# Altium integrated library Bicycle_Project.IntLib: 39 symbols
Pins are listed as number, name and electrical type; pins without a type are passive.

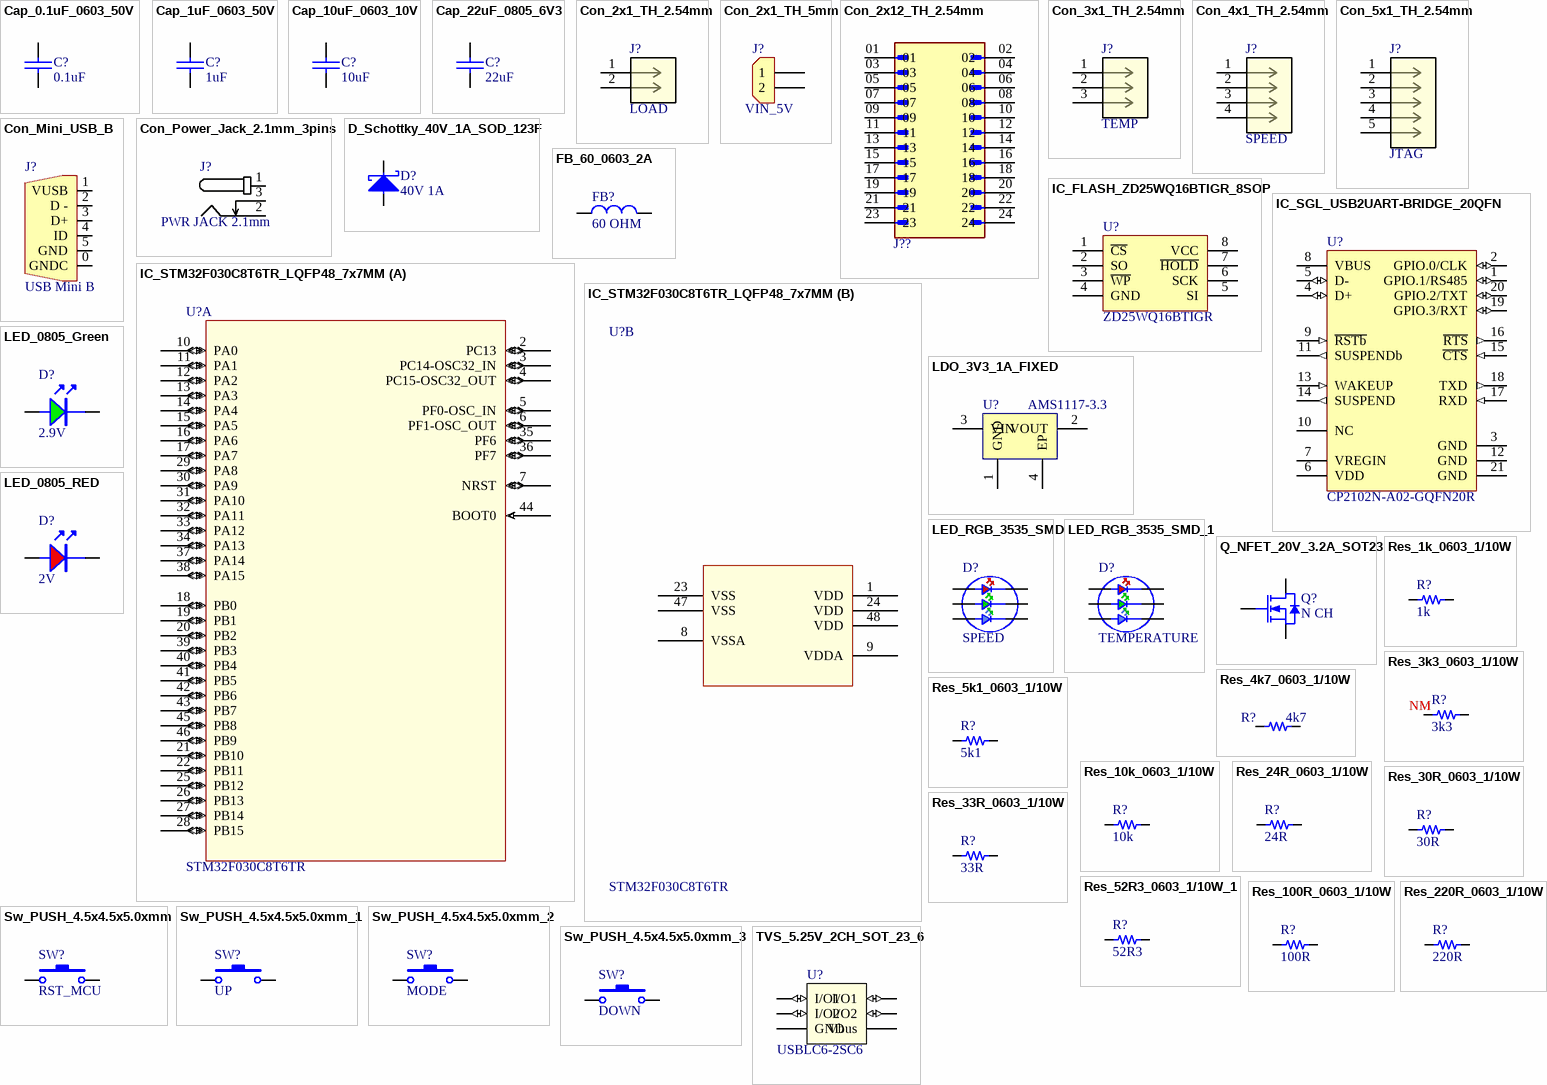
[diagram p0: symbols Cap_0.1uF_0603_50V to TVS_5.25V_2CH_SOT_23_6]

## Cap_0.1uF_0603_50V
designator C?, comment value 0.1uF  (hidden comment: 0.1uF 50V)
50V 100nF Y5V -20%~+80% 0603 Multilayer Ceramic Capacitors MLCC - SMD/SMT ROHS; Manufacturer: Walsin Tech Corp; Manufacturer Part Number: 0603F104Z500CT
footprint 0603_cap
pins: 1, 2

## Cap_1uF_0603_50V
designator C?, comment value 1uF  (hidden comment: 1uF 50V)
50V 1uF X5R ±10% 0603 Multilayer Ceramic Capacitors MLCC - SMD/SMT ROHS; Manufacturer: Samsung Electro-Mechanics; Manufacturer Part Number: CL10A105KB8NNNC
footprint 0603_cap
pins: 1, 2

## Cap_10uF_0603_10V
designator C?, comment value 10uF  (hidden comment: 10uF 10V)
10V 10uF X5R ±10% 0603 Multilayer Ceramic Capacitors MLCC - SMD/SMT ROHS; Manufacturer: CCTC; Manufacturer Part Number: TCC0603X5R106K100CT
footprint 0603_cap
pins: 1, 2

## Cap_22uF_0805_6V3
designator C?, comment value 22uF  (hidden comment: 22uF 6V3)
6.3V 22uF X5R ±20% 0805 Multilayer Ceramic Capacitors MLCC - SMD/SMT ROHS; Manufacturer: Samsung Electro-Mechanics; Manufacturer Part Number: CL21A226MQQNNNE
footprint 0603_cap
pins: 1, 2

## Con_2x1_TH_2.54mm
designator J?, comment LOAD
CONN HEADER VERT 2POS 2.54MM; Manufacturer: Samtec Inc.; Manufacturer Part Number: TS-102-T-A
footprint CON_2X1_TH_2.54mm
pins: 1, 2

## Con_2x1_TH_5mm
designator J?, comment VIN_5V
2POS 5MM; Manufacturer: JILN; Manufacturer Part Number: JL126-50002G01
footprint CON_2x1_TH_5MM
pins: 1, 2

## Con_2x12_TH_2.54mm
designator J??, comment 10129381-924001BLF  (value not drawn)
CONN HEADER VERT 24POS 2.54MM; Manufacturer: Amphenol ICC (FCI)
footprint CON_2x12_th_2.54MM
pins: 01, 02, 03, 04, 05, 06, 07, 08, 09, 10, 11, 12, 13, 14, 15, 16, 17, 18, 19, 20, 21, 22, 23, 24

## Con_3x1_TH_2.54mm
designator J?, comment TEMP
CONN HEADER VERT 3POS 2.54MM; Manufacturer: Samtec Inc.; Manufacturer Part Number: TS-103-T-A
footprint CON_3X1_TH_2.54mm
pins: 1, 2, 3

## Con_4x1_TH_2.54mm
designator J?, comment SPEED
CONN HEADER VERT 4POS 2.54MM; Manufacturer: Samtec Inc.; Manufacturer Part Number: TS-104-T-A
footprint CON_4X1_TH_2.54mm
pins: 1, 2, 3, 4

## Con_5x1_TH_2.54mm
designator J?, comment JTAG
CONN HEADER VERT 5POS 2.54MM; Manufacturer: Samtec Inc.; Manufacturer Part Number: TS-105-T-A
footprint CON_5X1_TH_2.54mm
pins: 1, 2, 3, 4, 5

## Con_Mini_USB_B
designator J?, comment USB Mini B
CONN RCPT USB2.0 MINI B SMD R/A; Manufacturer Part Number: KH-MINI-SMT-5P-Cu; Manufacturer: EDAC Inc.
footprint CON_5x1_SMD_miniUSB_B (20190328 / V-A.Patino)
pins: 0 GNDC, 1 VUSB, 2 D -, 3 D+, 4 ID, 5 GND

## Con_Power_Jack_2.1mm_3pins
designator J?, comment PWR JACK 2.1mm
CONN PWR JACK 2X5.5MM SOLDER; Manufacturer: HCTL; Manufacturer Part Number: HC-DC-005-2.0T
footprint CON_POWER_BARREL_2.1MM_3CONN (/ 20190222 / C-A.Serna.A)
pins: 1, 2, 3

## D_Schottky_40V_1A_SOD_123F
designator D?, comment 40V 1A
DIODE SCHOTTKY 40V 1A SOD123F; Manufacturer: Shanghai Prisemi Elec; Manufacturer Part Number: PSBD1DF40V1H
footprint SOD_123 (/ 20191030 / V-A.Patino)
pins: 1, 2

## FB_60_0603_2A
designator FB?, comment value 60 OHM  (hidden comment: 60OHM 2A)
2A 1 100mΩ 60Ω@100MHz ±25% 0603 Ferrite Beads ROHS; Manufacturer: TAI-TECH; Manufacturer Part Number: HCB1608KF-600T20
footprint 0603_fb
pins: 1, 2

## IC_FLASH_ZD25WQ16BTIGR_8SOP
designator U?, comment ZD25WQ16BTIGR
IC FLASH 16M SPI 85MHZ 8SOP; Manufacturer: Zetta
footprint SOIC_8_3.9mm (/ 20190225 / C-A.Serna.A)
pins: 1 ~{CS}, 2 SO, 3 ~{WP}, 4 GND, 5 SI, 6 SCK, 7 ~{HOLD}, 8 VCC

## IC_SGL_USB2UART-BRIDGE_20QFN
designator U?, comment CP2102N-A02-GQFN20R
IC USB TO UART BRIDGE QFN20; Manufacturer: Silicon Labs
footprint WFQFN_20_EP_3X3MM (QFN_20/ 20210809/ V-A.Patino)
pins: 1 GPIO.1/RS485 (io), 2 GPIO.0/CLK (io), 3 GND (power) "Ground", 4 D+ (io) "USB Data Positive", 5 D- (io) "USB Data Negative", 6 VDD (power) "Supply Power Input/5V Regulator Output", 7 VREGIN (power) "5V Regulator Input", 8 VBUS (power) "Digital Input. VBUS Sense Input. This pin should be connected to the VBUS signal of a USBnetwork. A 5 V signal on this pin indicates a USB network connection", 9 ~{RSTb} (in) "Active-low Reset", 10 NC "No Connect (leave this pin floating)", 11 SUSPENDb (out) "Digital Output. This pin is driven low when the device enters the USB suspend state.", 12 GND (power) "Ground", 13 WAKEUP (in) "Digital Input. Remote USB wakeup interrupt input.", 14 SUSPEND (out) "Digital Output. This pin is driven high when the device enters the USB suspend state", 15 ~{CTS} (in) "Digital Input. Clear To Send control input (active low).", 16 ~{RTS} (out) "Digital Output. Ready To Send control output (active low).", 17 RXD (in) "Digital Input. Asynchronous data input (UART Receive).", 18 TXD (out) "Digital Output. Asynchronous data output (UART Transmit)", 19 GPIO.3/RXT (io), 20 GPIO.2/TXT (io), 21 GND (power) "Ground"

## IC_STM32F030C8T6TR_LQFP48_7x7MM
designator U?, comment STM32F030C8T6TR
IC MCU 32BIT 64KB FLASH 48LQFP; Manufacturer: STMicroelectronics
footprint LQFP48_7x7mm
part A pins: 2 PC13 (io), 3 PC14-OSC32_IN (io), 4 PC15-OSC32_OUT (io), 5 PF0-OSC_IN (io), 6 PF1-OSC_OUT (io), 7 NRST (io), 10 PA0 (io), 11 PA1 (io), 12 PA2 (io), 13 PA3 (io), 14 PA4 (io), 15 PA5 (io), 16 PA6 (io), 17 PA7 (io), 18 PB0 (io), 19 PB1 (io), 20 PB2 (io), 21 PB10 (io), 22 PB11 (io), 25 PB12 (io), 26 PB13 (io), 27 PB14 (io), 28 PB15 (io), 29 PA8 (io), 30 PA9 (io), 31 PA10 (io), 32 PA11 (io), 33 PA12 (io), 34 PA13 (io), 35 PF6 (io), 36 PF7 (io), 37 PA14 (io), 38 PA15 (io), 39 PB3 (io), 40 PB4 (io), 41 PB5 (io), 42 PB6 (io), 43 PB7 (io), 44 BOOT0 (in), 45 PB8 (io), 46 PB9 (io)
part B pins: 1 VDD (power), 8 VSSA (power), 9 VDDA (power), 23 VSS (power), 24 VDD (power), 47 VSS (power), 48 VDD (power)

## LDO_3V3_1A_FIXED
designator U?, comment AMS1117-3.3
1A 60dB@(120Hz) Fixed 3.3V Positive 18V SOT-223 Linear Voltage Regulators (LDO) ROHS; Manufacturer: UMW(Youtai Semiconductor Co., Ltd.)
footprint SOT_223 (TO-261-4, TO-261AA / 20190829 / M-X.Arias)
pins: 1 GND, 2 VOUT, 3 VIN, 4 EP

## LED_0805_Green
designator D?, comment 2.9V
LED GREEN CLEAR 0805 SMD; Manufacturer: XINGLIGHT; Manufacturer Part Number: XL-2012UGC
footprint 0805_LED
pins: 1 A, 2

## LED_0805_RED
designator D?, comment 2V
LED RED CLEAR 0805 SMD; Manufacturer: XINGLIGHT; Manufacturer Part Number: XL-2012SURC
footprint 0805_LED
pins: 1 A, 2

## LED_RGB_3535_SMD
designator D?, comment SPEED
-30℃~+85℃ RGB 110° 3535(mm) Light Emitting Diodes (LED) ROHS; Manufacturer: Foshan NationStar Optoelectronics; Manufacturer Part Number: RS-3535MWAM
footprint RGB_NS_3.5X3.7
pins: 1, 2, 3, 4, 5, 6

## LED_RGB_3535_SMD_1
designator D?, comment TEMPERATURE
-30℃~+85℃ RGB 110° 3535(mm) Light Emitting Diodes (LED) ROHS; Manufacturer: Foshan NationStar Optoelectronics; Manufacturer Part Number: RS-3535MWAM
footprint RGB_NS_3.5X3.7
pins: 1, 2, 3, 4, 5, 6

## Q_NFET_20V_3.2A_SOT23
designator Q?, comment N CH
MOSFET N-CH 20V SOT23; Manufacturer: Doeshare; Manufacturer Part Number: DN2302S
footprint SOT_23_3 (TO-236-3, SC-59/ 20220901 / V-A.Patino)
pins: 1 G, 2 S, 3 D

## Res_1k_0603_1/10W
designator R?, comment value 1k  (hidden comment: 1k 1/10W)
RES SMD 1k OHM 5% 1/10W 0603; Manufacturer: FOJAN; Manufacturer Part Number: FRC0603J102 TS
footprint 0603_res (1608 Metric / 20190225 / C-A.Serna.A)
pins: 1, 2

## Res_3k3_0603_1/10W
designator R?, comment value 3k3  Usage: NM  (hidden comment: 3k3 1/10W)
RES SMD 3k3 OHM 5% 1/10W 0603; Manufacturer: FOJAN; Manufacturer Part Number: FRC0603J332 TS
footprint 0603_res (1608 Metric / 20190225 / C-A.Serna.A)
pins: 1, 2

## Res_4k7_0603_1/10W
designator R?, comment value 4k7  (hidden comment: 4k7 1/10W)
RES SMD 4k7 OHM 5% 1/10W 0603; Manufacturer: FOJAN; Manufacturer Part Number: FRC0603J472 TS
footprint 0603_res (1608 Metric / 20190225 / C-A.Serna.A)
pins: 1, 2

## Res_5k1_0603_1/10W
designator R?, comment value 5k1  (hidden comment: 5k1 1/10W)
RES SMD 5k1 OHM 5% 1/10W 0603; Manufacturer: FOJAN; Manufacturer Part Number: FRC0603J512 TS
footprint 0603_res (1608 Metric / 20190225 / C-A.Serna.A)
pins: 1, 2

## Res_10k_0603_1/10W
designator R?, comment value 10k  (hidden comment: 10k 1/10W)
RES SMD 10k OHM 5% 1/10W 0603; Manufacturer: FOJAN; Manufacturer Part Number: FRC0603J103TS
footprint 0603_res (1608 Metric / 20190225 / C-A.Serna.A)
pins: 1, 2

## Res_24R_0603_1/10W
designator R?, comment value 24R  (hidden comment: 24R 1/10W)
RES SMD 24R OHM 5% 1/10W 0603; Manufacturer: FOJAN; Manufacturer Part Number: FRC0603J240 TS
footprint 0603_res (1608 Metric / 20190225 / C-A.Serna.A)
pins: 1, 2

## Res_30R_0603_1/10W
designator R?, comment value 30R  (hidden comment: 30 1/10W)
RES SMD 30R OHM 1% 1/10W 0603; Manufacturer: FOJAN; Manufacturer Part Number: FRC0603F30R0TS
footprint 0603_res (1608 Metric / 20190225 / C-A.Serna.A)
pins: 1, 2

## Res_33R_0603_1/10W
designator R?, comment value 33R  (hidden comment: 33R 1/10W)
RES SMD 33R OHM 5% 1/10W 0603; Manufacturer: FOJAN; Manufacturer Part Number: FRC0603J330 TS
footprint 0603_res (1608 Metric / 20190225 / C-A.Serna.A)
pins: 1, 2

## Res_52R3_0603_1/10W_1
designator R?, comment value 52R3  (hidden comment: 52R3 1/10W)
RES SMD 52R3 OHM 1% 1/10W 0603; Manufacturer: FOJAN; Manufacturer Part Number: FRC0603F52R3TS
footprint 0603_res (1608 Metric / 20190225 / C-A.Serna.A)
pins: 1, 2

## Res_100R_0603_1/10W
designator R?, comment value 100R  (hidden comment: 100R 1/10W)
RES SMD 100R OHM 5% 1/10W 0603; Manufacturer: FOJAN; Manufacturer Part Number: FRC0603J101 TS
footprint 0603_res (1608 Metric / 20190225 / C-A.Serna.A)
pins: 1, 2

## Res_220R_0603_1/10W
designator R?, comment value 220R  (hidden comment: 220R 1/10W)
RES SMD 220R OHM 5% 1/10W 0603; Manufacturer: FOJAN; Manufacturer Part Number: FRC0603J221 TS
footprint 0603_res (1608 Metric / 20190225 / C-A.Serna.A)
pins: 1, 2

## Sw_PUSH_4.5x4.5x5.0xmm
designator SW?, comment RST_MCU
SWITCH TACTILE SPST-NO 0.05A 12V; Manufacturer: BZCN; Manufacturer Part Number: TSC015A05026A
footprint Sw_PUSH_4.5x4.5x5mm
pins: 1, 2

## Sw_PUSH_4.5x4.5x5.0xmm_1
designator SW?, comment UP
SWITCH TACTILE SPST-NO 0.05A 12V; Manufacturer: BZCN; Manufacturer Part Number: TSC015A05026A
footprint Sw_PUSH_4.5x4.5x5mm
pins: 1, 2

## Sw_PUSH_4.5x4.5x5.0xmm_2
designator SW?, comment MODE
SWITCH TACTILE SPST-NO 0.05A 12V; Manufacturer: BZCN; Manufacturer Part Number: TSC015A05026A
footprint Sw_PUSH_4.5x4.5x5mm
pins: 1, 2

## Sw_PUSH_4.5x4.5x5.0xmm_3
designator SW?, comment DOWN
SWITCH TACTILE SPST-NO 0.05A 12V; Manufacturer: BZCN; Manufacturer Part Number: TSC015A05026A
footprint Sw_PUSH_4.5x4.5x5mm
pins: 1, 2

## TVS_5.25V_2CH_SOT_23_6
designator U?, comment USBLC6-2SC6
TVS DIODE 5.25V 17V SOT23-6; Manufacturer: STMicroelectronics
footprint SOT_23_6 (/ 20190225 / V-A.Patino)
pins: 1 I/O1 (io), 2 GND (power), 3 I/O2 (io), 4 I/O2 (io), 5 Vbus (power), 6 I/O1 (io)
